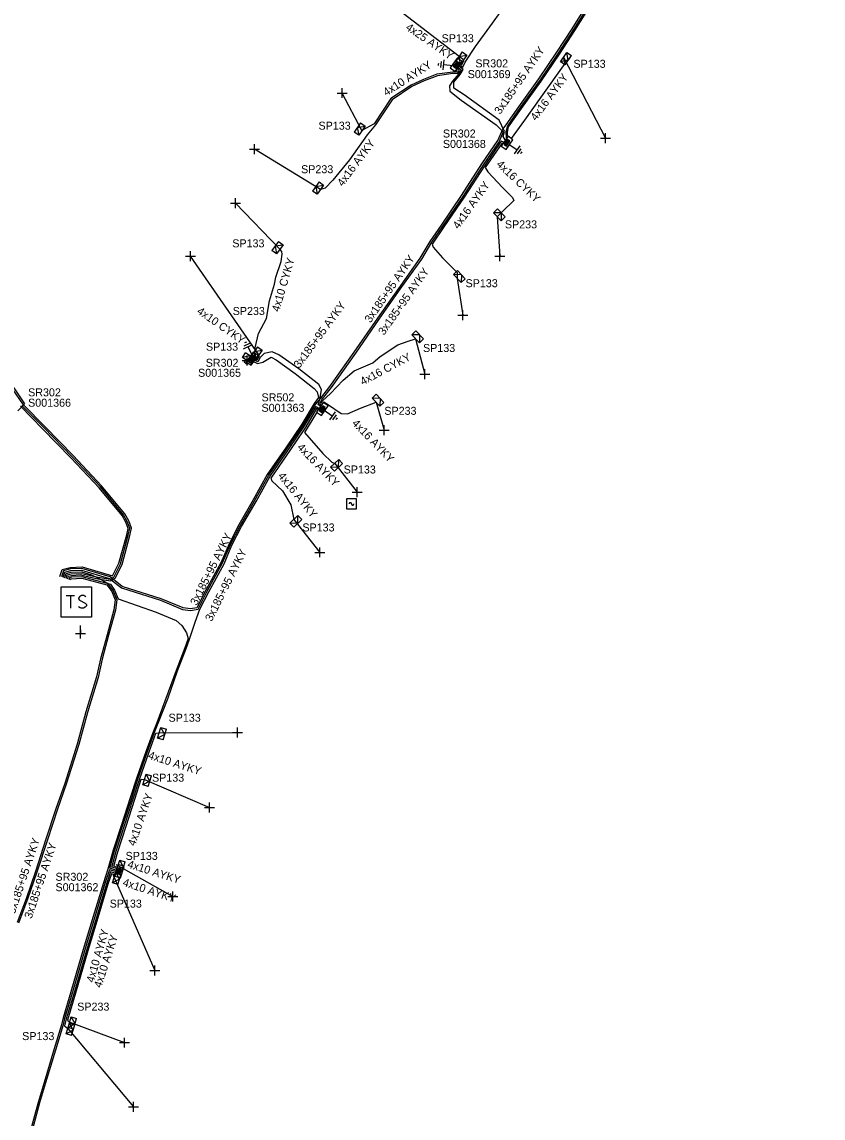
# Model space of a CAD drawing. Extents: x -763093 to -760976, y -1155572 to -1152009.
# Drawn here: x -761685 to -761585, y -1155309.8 to -1155172.9 of the extents above; entities that cross this region are included whole.
import ezdxf

# ---------------------------------------------------------------- set-up
doc = ezdxf.new("R2010")
doc.units = 0
for name, color, linetype in [('Vrstva 1', 7, 'Continuous'), ('Vrstva 14', 7, 'Continuous'), ('Vrstva 15', 7, 'Continuous'), ('Vrstva 25', 7, 'Continuous'), ('Vrstva 28', 7, 'Continuous'), ('Vrstva 29', 7, 'Continuous'), ('Vrstva 30', 7, 'Continuous'), ('Vrstva 31', 7, 'Continuous'), ('Vrstva 33', 7, 'Continuous'), ('Vrstva 34', 7, 'Continuous'), ('Vrstva 5', 7, 'Continuous'), ('Vrstva 52', 7, 'Continuous'), ('Vrstva 59', 7, 'Continuous'), ('Vrstva 6', 7, 'Continuous'), ('Vrstva 8', 7, 'Continuous'), ('Vrstva 9', 7, 'Continuous')]:
    doc.layers.add(name, color=color, linetype=linetype)

# ---------------------------------------------------------------- blocks, each defined once
blk = doc.blocks.new('NN800')
at = {"layer": 'Vrstva 1'}
for points in [[(-0.44, 0.44), (0.44, -0.44)], [(-0.44, -0.44), (0.44, 0.44)]]:
    blk.add_lwpolyline(points, dxfattribs=at)
blk = doc.blocks.new('NN620')
at = {"layer": 'Vrstva 8'}
for points in [[(0.75, 0), (-0.75, 0)], [(-0.75, 0), (-0.75, -0.75)], [(0.75, -0.75), (0.75, 0)], [(-0.75, -0.75), (0.75, -0.75)], [(0.37, -0.18), (-0.38, -0.18)], [(-0.38, -0.18), (-0.38, -0.56)], [(-0.38, -0.56), (0.37, -0.56)], [(0.32, -0.23), (-0.33, -0.23)], [(-0.33, -0.23), (-0.33, -0.51)], [(-0.33, -0.51), (0.32, -0.51)], [(0.27, -0.27), (-0.28, -0.27)], [(-0.28, -0.27), (-0.28, -0.46)], [(-0.28, -0.46), (0.27, -0.46)], [(0.23, -0.32), (-0.23, -0.32)], [(-0.23, -0.32), (-0.23, -0.42)], [(-0.23, -0.42), (0.23, -0.42)], [(-0.19, -0.37), (0.19, -0.37)], [(0.23, -0.42), (0.23, -0.32)], [(0.27, -0.46), (0.27, -0.27)], [(0.32, -0.51), (0.32, -0.23)], [(0.37, -0.56), (0.37, -0.18)]]:
    blk.add_lwpolyline(points, dxfattribs=at)
blk = doc.blocks.new('NN630')
at = {"layer": 'Vrstva 9'}
for points in [[(0, -0.7), (-0.7, 0)], [(-0.7, -0.7), (-0.7, 0), (0.7, 0), (0.7, -0.7)], [(-0.7, -0.7), (0.7, -0.7)], [(0, -0.7), (0.7, 0)]]:
    blk.add_lwpolyline(points, dxfattribs=at)
blk = doc.blocks.new('NN810')
at = {"layer": 'Vrstva 14'}
for points in [[(0, -0.64), (0, -1.89)], [(0.63, -1.89), (-0.62, -1.89)], [(0.39, -2.2), (-0.4, -2.2)], [(0, -2.52), (-0.12, -2.52)], [(0.14, -2.52), (0, -2.52)]]:
    blk.add_lwpolyline(points, dxfattribs=at)
blk = doc.blocks.new('NN740')
at = {"layer": 'Vrstva 1'}
for points in [[(0.62, 0.62), (-0.63, 0.62)], [(-0.63, 0.62), (-0.63, -0.63)], [(0, 0), (0, 0.01), (0, 0.03), (-0.01, 0.05), (-0.01, 0.06), (-0.02, 0.08), (-0.03, 0.09), (-0.04, 0.1), (-0.05, 0.11), (-0.06, 0.12), (-0.08, 0.13), (-0.09, 0.14), (-0.11, 0.14), (-0.12, 0.15), (-0.14, 0.15), (-0.15, 0.15), (-0.17, 0.15), (-0.18, 0.15), (-0.2, 0.15), (-0.21, 0.14), (-0.23, 0.13), (-0.24, 0.12), (-0.26, 0.11), (-0.27, 0.1), (-0.28, 0.09), (-0.29, 0.08), (-0.29, 0.06), (-0.3, 0.05), (-0.3, 0.03), (-0.31, 0.02), (-0.31, 0), (-0.31, 0)], [(0.62, -0.63), (0.62, 0.62)], [(-0.63, -0.63), (0.62, -0.63)], [(0, 0), (0, -0.02), (0, -0.03), (0.01, -0.05), (0.01, -0.06), (0.02, -0.08), (0.03, -0.09), (0.04, -0.1), (0.05, -0.11), (0.06, -0.12), (0.07, -0.13), (0.09, -0.14), (0.1, -0.15), (0.12, -0.15), (0.13, -0.15), (0.15, -0.15), (0.16, -0.15), (0.18, -0.15), (0.19, -0.15), (0.21, -0.14), (0.22, -0.14), (0.24, -0.13), (0.25, -0.12), (0.26, -0.11), (0.27, -0.09), (0.28, -0.08), (0.29, -0.07), (0.29, -0.05), (0.3, -0.04), (0.3, -0.02), (0.3, -0.01), (0.3, -0.01)]]:
    blk.add_lwpolyline(points, dxfattribs=at)
blk = doc.blocks.new('NN640')
at = {"layer": 'Vrstva 6'}
for points in [[(-1.89, 1.89), (1.89, 1.89)], [(-1.89, -1.89), (-1.89, 1.89)], [(1.89, 1.89), (1.89, -1.89)], [(-1.26, 0.79), (-0.22, 0.79)], [(-0.73, 0.79), (-0.73, -0.79)], [(1.2, 0.66), (0.94, 0.79), (0.66, 0.79), (0.41, 0.66), (0.28, 0.47), (0.28, 0.41), (0.41, 0.22), (1.13, -0.16), (1.26, -0.32), (1.26, -0.47), (1.13, -0.66), (0.91, -0.79), (0.63, -0.79), (0.5, -0.73), (0.28, -0.6)], [(1.89, -1.89), (-1.89, -1.89)]]:
    blk.add_lwpolyline(points, dxfattribs=at)

msp = doc.modelspace()

# ---------------------------------------------------------------- linework, layer by layer
at = {"layer": 'Vrstva 5'}
for points in [[(-761584.97, -1155130.11), (-761585.14, -1155130.06), (-761586.62, -1155131.6), (-761587.78, -1155133.39), (-761590.31, -1155137.08), (-761592.56, -1155140.53), (-761594.59, -1155143.27), (-761596.73, -1155146.36), (-761598.93, -1155149.53), (-761600.22, -1155151.12), (-761602.63, -1155154.51), (-761604.92, -1155157.58), (-761607.52, -1155161.58), (-761609.19, -1155163.76), (-761610.63, -1155165.31), (-761611.93, -1155167.47), (-761614.02, -1155170.44), (-761616.14, -1155173.83), (-761618.04, -1155176.77), (-761620.3, -1155180.1), (-761622.77, -1155183.58), (-761624.38, -1155185.85), (-761624.56, -1155186.62), (-761624.53, -1155187.36)], [(-761630.28, -1155178.3), (-761629.96, -1155178.53), (-761629.66, -1155177.89), (-761628.37, -1155175.94), (-761626.22, -1155173.02), (-761624.33, -1155170.35), (-761622.41, -1155167.72), (-761621.65, -1155166.55), (-761621.83, -1155166.08), (-761621.4, -1155165.91), (-761621.4, -1155165.48), (-761620.85, -1155165.36), (-761611.49, -1155151.86), (-761611.59, -1155151.35), (-761611.19, -1155151.16), (-761611.16, -1155150.72)], [(-761624.36, -1155187.16), (-761624.38, -1155186.65), (-761624.22, -1155185.97), (-761622.61, -1155183.7), (-761620.16, -1155180.25), (-761617.87, -1155176.88), (-761615.97, -1155173.94), (-761613.85, -1155170.55), (-761611.76, -1155167.58), (-761610.47, -1155165.43), (-761608.85, -1155163.68), (-761608.6, -1155163.63), (-761608.21, -1155163.82)], [(-761679.84, -1155242.24), (-761679.63, -1155241.62), (-761678.89, -1155241.41), (-761677.54, -1155241.36), (-761674.06, -1155242.4), (-761672.56, -1155243.57), (-761667.67, -1155245.1), (-761664.93, -1155246.27), (-761663.92, -1155246.4), (-761663, -1155246.24), (-761661.85, -1155243.96), (-761659.93, -1155240.46), (-761658.94, -1155238.14), (-761657.74, -1155235.81), (-761655.93, -1155232.69), (-761654.14, -1155229.51), (-761654.15, -1155229.48), (-761651.79, -1155226.05), (-761649.85, -1155223.22), (-761648.32, -1155220.66), (-761647.66, -1155219.87), (-761646.55, -1155218.43), (-761643.51, -1155214.12), (-761640.57, -1155209.89), (-761637.95, -1155206.15), (-761635.26, -1155202.39), (-761634.02, -1155200.29), (-761632.62, -1155198.26), (-761630.1, -1155194.55), (-761627.56, -1155190.61), (-761625.57, -1155187.69), (-761624.96, -1155186.26), (-761624.54, -1155185.73), (-761622.93, -1155183.46), (-761620.46, -1155179.99), (-761618.21, -1155176.66), (-761616.31, -1155173.72), (-761614.19, -1155170.33)], [(-761630.19, -1155178.14), (-761630.05, -1155178.23), (-761629.8, -1155177.73), (-761629.86, -1155177.6)], [(-761623.88, -1155187.42), (-761622.19, -1155185.16), (-761620.16, -1155182.25), (-761617.16, -1155178.08), (-761617.36, -1155177.26)], [(-761630.5, -1155178.6), (-761630.14, -1155178.86), (-761630.43, -1155179.35), (-761631.25, -1155180.28), (-761631.61, -1155180.84), (-761631.57, -1155181.54), (-761630.14, -1155182.66), (-761625.78, -1155185.71), (-761624.89, -1155186.58), (-761625.4, -1155187.8), (-761627.39, -1155190.72), (-761629.93, -1155194.66), (-761632.46, -1155198.37), (-761633.86, -1155200.4), (-761635.1, -1155202.51), (-761637.79, -1155206.27), (-761640.41, -1155210.01), (-761643.35, -1155214.24), (-761646.39, -1155218.55), (-761647.5, -1155219.96), (-761647.82, -1155220.57), (-761647.64, -1155220.71)], [(-761630.61, -1155178.75), (-761630.4, -1155178.92), (-761630.66, -1155179.35), (-761631.19, -1155179.33), (-761633.11, -1155179.59), (-761634.76, -1155180.24), (-761636.31, -1155180.93), (-761638.77, -1155182.59), (-761640.84, -1155185.73), (-761641.87, -1155186.99), (-761644.07, -1155190.1), (-761646.15, -1155192.62), (-761647.11, -1155193.64), (-761647.72, -1155193.82)], [(-761630.73, -1155178.92), (-761630.66, -1155178.96), (-761630.77, -1155179.14), (-761631.21, -1155179.13), (-761633.17, -1155179.39), (-761634.84, -1155180.06), (-761636.41, -1155180.75), (-761638.91, -1155182.45), (-761641, -1155185.61), (-761642.54, -1155186.45)], [(-761624.66, -1155187.58), (-761624.9, -1155187.17), (-761624.72, -1155186.57), (-761625.39, -1155185.14), (-761629.78, -1155181.99), (-761631.07, -1155181.13), (-761631.07, -1155180.38), (-761630.26, -1155179.45), (-761629.88, -1155178.81), (-761630.39, -1155178.45)], [(-761624.87, -1155187.91), (-761625.14, -1155187.78), (-761627.23, -1155190.84), (-761629.76, -1155194.77), (-761632.3, -1155198.48), (-761633.78, -1155200.63), (-761633.64, -1155201.01), (-761632.48, -1155202.35), (-761630.66, -1155204.16), (-761630.63, -1155204.93)], [(-761625, -1155188.07), (-761625.08, -1155188.04), (-761627.14, -1155191.06), (-761626.83, -1155191.58), (-761624.99, -1155193.56), (-761623.76, -1155194.82), (-761623.59, -1155195.17), (-761625, -1155196.56), (-761625.64, -1155197.22)], [(-761697.53, -1155193.48), (-761697.67, -1155193.63), (-761696.34, -1155194.74), (-761694.98, -1155196.37), (-761694.02, -1155198.43), (-761694.16, -1155199.09), (-761695.95, -1155200.74), (-761698.52, -1155203.23), (-761699.31, -1155204.34), (-761699.13, -1155205.25), (-761697.71, -1155206.9), (-761693.15, -1155211.49), (-761688.11, -1155216.52), (-761686.01, -1155218.57), (-761684.65, -1155220.57), (-761685.49, -1155221.45)], [(-761655.93, -1155215.16), (-761655.86, -1155213.57), (-761655.44, -1155211.78), (-761654.47, -1155209.92), (-761654.08, -1155207.73), (-761653.47, -1155205.61), (-761653.28, -1155204.74), (-761652.63, -1155202.78), (-761652.5, -1155201.9), (-761652.54, -1155201.53), (-761652.79, -1155201.27)], [(-761647.51, -1155220.55), (-761647.62, -1155220.46), (-761647.45, -1155220.2), (-761646.48, -1155219.28), (-761644.9, -1155217.61), (-761643.51, -1155216.47), (-761641.16, -1155215.46), (-761640.26, -1155214.68), (-761638.06, -1155213.22), (-761636.76, -1155212.75), (-761635.84, -1155212.45)], [(-761656, -1155215.34), (-761655.58, -1155215.56), (-761654.92, -1155215.37), (-761653.87, -1155214.73), (-761653.26, -1155215.07), (-761650.88, -1155216.79), (-761648.49, -1155218.65), (-761648.14, -1155219.07), (-761647.97, -1155219.78), (-761648.49, -1155220.55), (-761650.02, -1155223.11), (-761651.96, -1155225.94), (-761654.35, -1155229.42), (-761656.1, -1155232.59), (-761657.92, -1155235.71), (-761659.12, -1155238.05), (-761660.11, -1155240.37), (-761662.03, -1155243.87), (-761663.13, -1155246.06), (-761663.92, -1155246.2), (-761664.87, -1155246.07), (-761667.61, -1155244.92), (-761672.48, -1155243.39), (-761673.97, -1155242.21), (-761677.51, -1155241.16), (-761678.92, -1155241.21), (-761679.78, -1155241.45), (-761680.04, -1155242.21)], [(-761647.74, -1155220.87), (-761648.02, -1155220.66), (-761647.74, -1155219.81), (-761647.58, -1155218.78), (-761647.92, -1155218.16), (-761650.4, -1155216.2), (-761652.92, -1155214.47), (-761653.75, -1155214.07), (-761654.73, -1155214.27), (-761655.23, -1155214.78), (-761655.54, -1155215.34), (-761655.88, -1155215.17)], [(-761655.76, -1155215.01), (-761655.62, -1155215.08), (-761655.34, -1155214.58), (-761655.39, -1155214.44)], [(-761679.28, -1155242.45), (-761679.16, -1155242.11), (-761678.79, -1155242.01), (-761677.65, -1155241.95), (-761675.51, -1155242.43), (-761673.93, -1155242.69), (-761673.36, -1155242.36), (-761672.49, -1155240.64), (-761671.51, -1155237.03), (-761671.3, -1155236.1), (-761671.65, -1155235.21), (-761672.12, -1155234.32), (-761675.04, -1155230.81), (-761678.59, -1155227.05), (-761682.12, -1155223.41), (-761684.79, -1155220.72), (-761686.17, -1155218.7)], [(-761680.23, -1155242.14), (-761679.94, -1155241.29), (-761678.95, -1155241.01), (-761677.48, -1155240.96), (-761673.66, -1155242.08), (-761672.87, -1155240.5), (-761671.89, -1155236.93), (-761671.72, -1155236.14), (-761672.01, -1155235.37), (-761672.46, -1155234.54), (-761675.34, -1155231.07), (-761678.87, -1155227.33), (-761682.4, -1155223.69), (-761685.16, -1155220.89)], [(-761679.46, -1155242.36), (-761679.32, -1155241.95), (-761678.82, -1155241.81), (-761677.54, -1155241.76), (-761675.47, -1155242.23), (-761673.96, -1155242.48), (-761673.51, -1155242.22), (-761672.68, -1155240.57), (-761671.7, -1155236.98), (-761671.51, -1155236.12), (-761671.83, -1155235.29), (-761672.29, -1155234.43), (-761675.19, -1155230.94), (-761678.73, -1155227.19), (-761682.26, -1155223.55), (-761684.99, -1155220.78)], [(-761673.25, -1155278.83), (-761674.01, -1155278.59), (-761673.42, -1155276.41), (-761672.38, -1155273.21), (-761671.28, -1155269.85), (-761670.51, -1155267.45), (-761669.3, -1155264), (-761668.47, -1155261.73), (-761667.96, -1155260.48), (-761666.74, -1155257.29), (-761665.56, -1155253.95), (-761664.46, -1155251.13), (-761664.11, -1155250.09), (-761663.36, -1155247.85), (-761662.76, -1155246.22), (-761661.67, -1155244.05), (-761659.75, -1155240.55), (-761658.76, -1155238.23), (-761657.56, -1155235.91), (-761655.76, -1155232.79), (-761653.99, -1155229.6), (-761651.63, -1155226.17), (-761649.69, -1155223.34), (-761648.26, -1155220.91), (-761647.9, -1155221.1)], [(-761648.02, -1155221.3), (-761648.22, -1155221.18), (-761649.53, -1155223.46), (-761649.87, -1155223.96), (-761651.46, -1155226.28), (-761653.93, -1155229.86), (-761653.79, -1155230.18), (-761652.44, -1155231.43), (-761651.43, -1155233.2), (-761651.03, -1155235.01)], [(-761647.34, -1155220.39), (-761647.29, -1155220.32), (-761646.84, -1155220.61), (-761645.13, -1155221.78), (-761644.35, -1155221.84), (-761642.72, -1155221.14), (-761640.78, -1155220.38)], [(-761648.21, -1155221.69), (-761649.7, -1155224.15), (-761647.41, -1155226.79), (-761646.28, -1155227.86), (-761645.94, -1155228.02)], [(-761679.66, -1155242.33), (-761679.47, -1155241.78), (-761678.85, -1155241.61), (-761677.55, -1155241.56), (-761676.29, -1155241.93), (-761675.49, -1155242.33), (-761674.28, -1155242.98), (-761673.59, -1155243.94), (-761673.14, -1155245.05), (-761673.3, -1155246.36), (-761674.16, -1155249.48), (-761674.97, -1155252.47), (-761675.48, -1155254.75), (-761676.79, -1155259.12), (-761677.87, -1155263.15), (-761679.45, -1155268.07), (-761680.56, -1155271.22), (-761681.79, -1155275.03), (-761683.12, -1155279.07), (-761684.28, -1155282.47), (-761685.41, -1155285.46)], [(-761679.09, -1155242.52), (-761679.01, -1155242.28), (-761678.76, -1155242.21), (-761677.52, -1155242.16), (-761673.93, -1155243.12), (-761673.41, -1155243.84), (-761672.97, -1155244.95), (-761668.23, -1155246.61), (-761665.72, -1155247.66), (-761665, -1155248.26), (-761664.44, -1155249.2), (-761664.25, -1155249.89), (-761664.64, -1155251.07), (-761665.74, -1155253.87), (-761668.14, -1155260.42), (-761668.66, -1155261.66), (-761669.49, -1155263.94), (-761670.7, -1155267.39), (-761671.47, -1155269.79), (-761672.57, -1155273.15), (-761673.61, -1155276.35), (-761674.25, -1155278.69), (-761674.82, -1155280.42), (-761676.08, -1155284.62), (-761677.32, -1155288.74), (-761678.86, -1155294.02), (-761679.84, -1155297.29), (-761680.04, -1155298.14), (-761681, -1155301.27), (-761682.22, -1155305.35), (-761682.97, -1155307.84), (-761684.23, -1155312.58)], [(-761678.9, -1155242.58), (-761678.85, -1155242.44), (-761677.52, -1155242.36), (-761674.39, -1155243.19), (-761673.77, -1155244.04), (-761673.35, -1155245.08), (-761673.5, -1155246.32), (-761674.36, -1155249.42), (-761675.17, -1155252.43), (-761675.68, -1155254.69), (-761676.99, -1155259.06), (-761678.07, -1155263.09), (-761679.63, -1155268.01), (-761680.74, -1155271.16), (-761681.99, -1155274.97), (-761683.3, -1155279.01), (-761684.46, -1155282.41), (-761685.59, -1155285.38)], [(-761673.19, -1155278.64), (-761673.77, -1155278.45), (-761673.22, -1155276.47), (-761672.18, -1155273.27), (-761671.08, -1155269.91), (-761670.31, -1155267.51), (-761669.11, -1155264.06), (-761668.25, -1155261.71), (-761667.83, -1155261.66)], [(-761673.16, -1155278.44), (-761673.52, -1155278.32), (-761673.03, -1155276.53), (-761671.99, -1155273.33), (-761670.89, -1155269.97), (-761670.1, -1155267.48), (-761669.68, -1155267.49)], [(-761673.31, -1155279.02), (-761674.04, -1155278.79), (-761674.63, -1155280.48), (-761675.89, -1155284.68), (-761677.13, -1155288.8), (-761678.67, -1155294.08), (-761679.65, -1155297.35), (-761679.83, -1155298.15), (-761680.8, -1155301.33), (-761682.02, -1155305.41), (-761682.77, -1155307.9), (-761684.03, -1155312.62)], [(-761673.38, -1155279.21), (-761673.92, -1155279.03), (-761674.43, -1155280.54), (-761675.69, -1155284.74), (-761676.93, -1155288.86), (-761678.47, -1155294.14), (-761679.45, -1155297.41), (-761679.67, -1155298.28), (-761679.26, -1155298.61)], [(-761673.09, -1155278.31), (-761673.19, -1155278.11), (-761672.99, -1155278.24)], [(-761673.44, -1155279.4), (-761673.79, -1155279.28), (-761674.24, -1155280.6), (-761675.5, -1155284.8), (-761676.74, -1155288.92), (-761678.28, -1155294.2), (-761679.3, -1155297.59), (-761679.02, -1155297.83)], [(-761673.47, -1155279.54), (-761673.59, -1155279.51), (-761673.46, -1155279.73)]]:
    msp.add_lwpolyline(points, dxfattribs=at)
at = {"layer": 'Vrstva 52'}
msp.add_lwpolyline([(-761656.73, -1155215.55), (-761656.87, -1155215.65), (-761657.23, -1155215.38), (-761657.09, -1155215.2), (-761656.88, -1155215.17)], dxfattribs=at)
at = {"layer": 'Vrstva 59'}
for points in [[(-761629.86, -1155177.6), (-761639.56, -1155170.13)], [(-761617.36, -1155177.26), (-761612.13, -1155187.38)], [(-761642.54, -1155186.45), (-761645, -1155181.75)], [(-761647.72, -1155193.82), (-761655.94, -1155188.75)], [(-761652.79, -1155201.27), (-761658.31, -1155195.5)], [(-761625.64, -1155197.22), (-761625.31, -1155202.13)], [(-761655.39, -1155214.44), (-761663.94, -1155202.13)], [(-761630.63, -1155204.93), (-761629.94, -1155209.5)], [(-761635.84, -1155212.45), (-761634.69, -1155216.88)], [(-761640.78, -1155220.38), (-761639.75, -1155223.88)], [(-761645.94, -1155228.02), (-761643.13, -1155231.63)], [(-761651.03, -1155235.01), (-761647.81, -1155239.13)], [(-761677.7, -1155248.27), (-761677.68, -1155249.28)], [(-761667.83, -1155261.66), (-761658.06, -1155261.63)], [(-761669.68, -1155267.49), (-761661.56, -1155271)], [(-761672.99, -1155278.24), (-761666.13, -1155282.13)], [(-761673.46, -1155279.73), (-761668.38, -1155291.38)], [(-761679.02, -1155297.83), (-761672.19, -1155300.38)], [(-761679.26, -1155298.61), (-761671.06, -1155308.38)]]:
    msp.add_lwpolyline(points, dxfattribs=at)

# ---------------------------------------------------------------- block references
at = {"layer": 'Vrstva 15'}
for p, rotation in [((-761630.46, -1155178.43), -96.18533113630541), ((-761624.73, -1155187.77), 55.2335915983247), ((-761655.93, -1155215.15), -154.60375182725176), ((-761647.79, -1155221.01), 55.2535083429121)]:
    msp.add_blockref('NN810', p, dxfattribs=dict(at, rotation=rotation))
at = {"layer": 'Vrstva 25'}
msp.add_blockref('NN640', (-761678.2, -1155245.33), dxfattribs=at)
at = {"layer": 'Vrstva 28'}
for p, rotation in [((-761630.46, -1155178.43), -124.57419165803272), ((-761624.73, -1155187.77), 55.23359167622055), ((-761655.93, -1155215.15), -124.84043066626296), ((-761647.79, -1155221.01), 55.25350828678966), ((-761673.18, -1155278.85), 72.62456117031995)]:
    msp.add_blockref('NN620', p, dxfattribs=dict(at, rotation=rotation))
at = {"layer": 'Vrstva 31'}
for p, rotation in [((-761629.86, -1155177.6), -124.7887194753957), ((-761617.36, -1155177.26), 55.2335915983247), ((-761642.54, -1155186.45), -124.75799442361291), ((-761647.72, -1155193.82), -124.84043053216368), ((-761625.64, -1155197.22), 133.94559450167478), ((-761652.79, -1155201.27), -126.7325033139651), ((-761630.63, -1155204.93), 133.45918890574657), ((-761635.84, -1155212.45), 133.92246385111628), ((-761656.88, -1155215.17), 145.45482780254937), ((-761655.39, -1155214.44), -124.783636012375), ((-761640.78, -1155220.38), 133.77144721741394), ((-761645.94, -1155228.02), 43.73897502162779), ((-761651.03, -1155235.01), 43.733588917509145), ((-761667.83, -1155261.66), 72.68167506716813), ((-761669.68, -1155267.49), 72.68167500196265), ((-761672.99, -1155278.24), 72.62456117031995), ((-761673.46, -1155279.73), 72.62456110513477), ((-761679.26, -1155298.61), 72.62456117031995), ((-761679.02, -1155297.83), 74.38919153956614)]:
    msp.add_blockref('NN630', p, dxfattribs=dict(at, rotation=rotation))
at = {"layer": 'Vrstva 34'}
for p, rotation in [((-761645, -1155181.75), 45), ((-761612.13, -1155187.38), 45), ((-761655.94, -1155188.75), 44.99999995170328), ((-761658.31, -1155195.5), 45), ((-761663.94, -1155202.13), 44.99999995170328), ((-761625.31, -1155202.13), 45), ((-761629.94, -1155209.5), 44.99999995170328), ((-761656.88, -1155215.17), 45), ((-761634.69, -1155216.88), 44.99999995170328), ((-761639.75, -1155223.88), 45), ((-761643.13, -1155231.63), 45), ((-761647.81, -1155239.13), 45), ((-761677.68, -1155249.28), 45), ((-761658.06, -1155261.63), 45), ((-761661.56, -1155271), 45), ((-761666.13, -1155282.13), 45), ((-761668.38, -1155291.38), 45), ((-761672.19, -1155300.38), 44.99999995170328), ((-761671.06, -1155308.38), 45)]:
    msp.add_blockref('NN800', p, dxfattribs=dict(at, rotation=rotation))
msp.add_blockref('NN740', (-761643.84, -1155233.08), dxfattribs=at)

# ---------------------------------------------------------------- texts
at = {"layer": 'Vrstva 29'}
for s, p in [('S001369', (-761629.34, -1155179.89)), ('S001368', (-761632.43, -1155188.61)), ('S001365', (-761662.99, -1155217.2)), ('S001366', (-761684.21, -1155220.94)), ('S001363', (-761655.07, -1155221.57)), ('S001362', (-761680.79, -1155281.46))]:
    msp.add_text(s, height=1, dxfattribs=at).set_placement(p)
at = {"layer": 'Vrstva 30'}
for s, p in [('SR302', (-761628.38, -1155178.55)), ('SR302', (-761632.43, -1155187.31)), ('SR302', (-761662.04, -1155215.95)), ('SR302', (-761684.21, -1155219.64)), ('SR502', (-761655.07, -1155220.27)), ('SR302', (-761680.79, -1155280.16))]:
    msp.add_text(s, height=1, dxfattribs=at).set_placement(p)
at = {"layer": 'Vrstva 33'}
for s, p in [('SP133', (-761632.59, -1155175.41)), ('SP133', (-761616.13, -1155178.6)), ('SP133', (-761647.96, -1155186.33)), ('SP233', (-761650.13, -1155191.77)), ('SP233', (-761624.69, -1155198.66)), ('SP133', (-761658.72, -1155201.03)), ('SP133', (-761629.6, -1155206.01)), ('SP233', (-761658.67, -1155209.48)), ('SP133', (-761662.01, -1155213.94)), ('SP133', (-761634.91, -1155214.1)), ('SP233', (-761639.74, -1155221.95)), ('SP133', (-761644.82, -1155229.28)), ('SP133', (-761649.97, -1155236.52)), ('SP133', (-761666.68, -1155260.29)), ('SP133', (-761668.74, -1155267.78)), ('SP133', (-761672.04, -1155277.55)), ('SP133', (-761674.03, -1155283.51)), ('SP233', (-761678.08, -1155296.38)), ('SP133', (-761684.95, -1155300.06))]:
    msp.add_text(s, height=1, dxfattribs=at).set_placement(p)
at = {"layer": 'Vrstva 6'}
for s, rotation, p in [('4x25 AYKY', 325.303, (-761637.17, -1155173.76)), ('3x185+95 AYKY', 55.272, (-761625.28, -1155184.5)), ('4x10 AYKY', 32.6, (-761639.5, -1155182.18)), ('4x16 AYKY', 53.509, (-761620.8, -1155185.29)), ('4x16 AYKY', 53.281, (-761644.93, -1155193.5)), ('4x16 CYKY', 316.555, (-761625.84, -1155190.76)), ('4x16 AYKY', 54.445, (-761630.49, -1155198.82)), ('4x10 CYKY', 73.61, (-761652.88, -1155209.15)), ('3x185+95 AYKY', 55.505, (-761641.47, -1155210.54)), ('3x185+95 AYKY', 54.753, (-761639.78, -1155212.08)), ('3x185+95 AYKY', 53.575, (-761650.35, -1155216.21)), ('4x10 CYKY', 325.035, (-761663.23, -1155209.21)), ('4x16 CYKY', 28.118, (-761642.43, -1155218.3)), ('4x16 AYKY', 313.836, (-761643.86, -1155223.08)), ('4x16 AYKY', 314.029, (-761650.71, -1155226.09)), ('4x16 AYKY', 308.863, (-761653.09, -1155229.61)), ('3x185+95 AYKY', 63.358, (-761663.15, -1155245.84)), ('3x185+95 AYKY', 63.365, (-761661.29, -1155247.84)), ('4x10 AYKY', 342.192, (-761669.3, -1155264.88)), ('4x10 AYKY', 70.807, (-761670.87, -1155275.9)), ('3x185+95 AYKY', 71.446, (-761685.87, -1155284.36)), ('3x185+95 AYKY', 71.447, (-761683.78, -1155284.97)), ('4x10 AYKY', 342.413, (-761671.89, -1155278.48)), ('4x10 AYKY', 341.841, (-761672.48, -1155280.76)), ('4x10 AYKY', 73.936, (-761676.02, -1155292.94)), ('4x10 AYKY', 71.983, (-761675.09, -1155293.6))]:
    msp.add_text(s, height=1, rotation=rotation, dxfattribs=at).set_placement(p)

doc.saveas('drawing.dxf')
